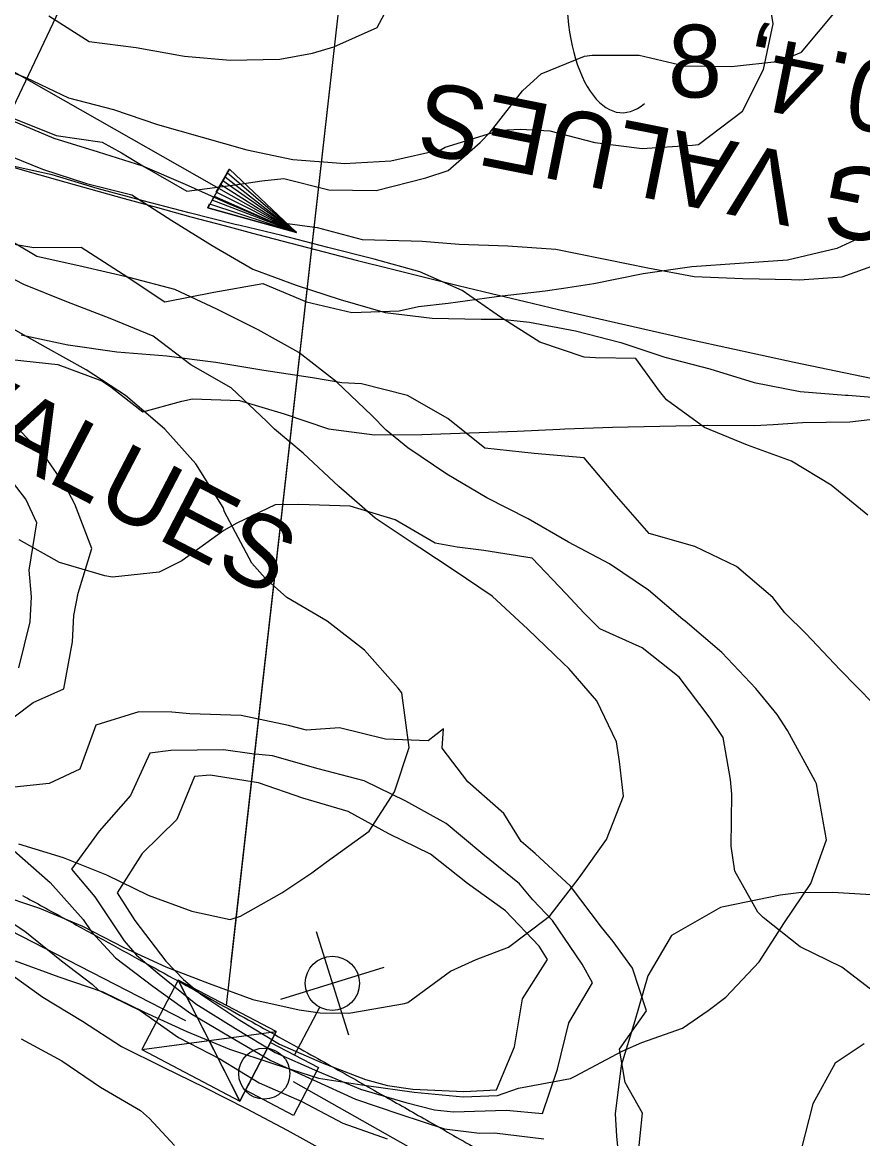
# Model space of a CAD drawing. Extents: x 1638506 to 1658005, y 834807 to 846788.
# Drawn here: x 1640269.4 to 1640408.1, y 842523.2 to 842707.5 of the extents above; entities that cross this region are included whole.
import ezdxf

# ---------------------------------------------------------------- set-up
doc = ezdxf.new("R2010")
doc.units = 0
for name, color, linetype in [('Default', 7, 'Continuous'), ('Old_Level_1', 7, 'Continuous'), ('Old_Level_2', 7, 'Continuous'), ('Scratch_Level_0', 7, 'Continuous')]:
    doc.layers.add(name, color=color, linetype=linetype)

msp = doc.modelspace()

# ---------------------------------------------------------------- linework, layer by layer
at = {"layer": 'Default'}
for p, q in [((1640114.23, 842786.79), (1640314.63, 842672.83)), ((1640303.08, 842545.23), (1640327.81, 842764.74)), ((1640303.88, 842552.36), (1640327.15, 842758.82)), ((1640060.76, 842664.16), (1640296.3, 842542.72)), ((1640317.9, 842557.44), (1640323.23, 842540.37)), ((1640312.05, 842546.24), (1640329.11, 842551.55)), ((1640295.12, 842549.41), (1640305.28, 842529.43)), ((1640320.57, 842548.92), (1640320.57, 842548.92)), ((1640316.26, 842547.55), (1640316.26, 842547.55)), ((1640314.33, 842537.04), (1640318.49, 842544.96)), ((1640289.09, 842537.94), (1640311.31, 842540.91)), ((1640314.09, 842532.64), (1640637.56, 842350.59))]:
    msp.add_line(p, q, dxfattribs=at)
msp.add_lwpolyline([(1640301.77, 842680.14), (1640302.13, 842680.79), (1640314.63, 842672.83), (1640302.47, 842681.39), (1640302.84, 842682.03), (1640314.63, 842672.83), (1640303.2, 842682.67), (1640303.57, 842683.32), (1640314.63, 842672.83), (1640299.98, 842676.9), (1640300.3, 842677.57), (1640314.63, 842672.83), (1640300.71, 842678.19), (1640301.03, 842678.86), (1640314.63, 842672.83), (1640301.4, 842679.5), (1640303.57, 842683.32), (1640299.98, 842676.9), (1640314.63, 842672.83), (1640303.57, 842683.32)], dxfattribs=at)
for points in [[(1640289.09, 842537.94), (1640305.28, 842529.43), (1640311.31, 842540.91), (1640295.12, 842549.41)], [(1640300.2, 842539.42), (1640295.12, 842549.41), (1640289.09, 842537.94)], [(1640300.2, 842539.42), (1640311.31, 842540.91), (1640305.28, 842529.43)], [(1640306.22, 842531.22), (1640310.37, 842539.12), (1640318.29, 842534.96), (1640314.14, 842527.06)]]:
    msp.add_lwpolyline(points, close=True, dxfattribs=at)
msp.add_circle((1640320.56, 842548.88), 4.47, dxfattribs=at)
msp.add_ellipse((1640368.8, 842713.14), major_axis=(-0.49, -20.52), ratio=0.466223, start_param=4.712389, end_param=6.681485, dxfattribs=at)
at = {"layer": 'Old_Level_1'}
for points in [[(1640262.94, 842701.14), (1640270.07, 842698.37), (1640277.01, 842695.06), (1640284.45, 842693.14), (1640291.69, 842690.67), (1640299.08, 842688.6), (1640306.46, 842686.5), (1640314.01, 842684.89), (1640321.93, 842684.27), (1640322.53, 842684.23), (1640330.21, 842684.65), (1640338.49, 842686.56), (1640339.17, 842686.9), (1640348.33, 842689.72), (1640351.63, 842689.92), (1640356.44, 842689.63), (1640363.89, 842687.72), (1640371.67, 842686.72), (1640379.99, 842687.24), (1640380.97, 842687.38), (1640388.22, 842692.89), (1640391.7, 842699.76), (1640393.32, 842707.31), (1640391.9, 842715.97)], [(1640273.79, 842708.59), (1640280.4, 842704.37), (1640288.17, 842703.36), (1640295.82, 842702.02), (1640296.16, 842701.97), (1640303.69, 842701.27), (1640311.89, 842701.43), (1640317.29, 842702.42), (1640320.78, 842703.49), (1640327.93, 842706.69), (1640331.59, 842713.5)], [(1640267.53, 842691.39), (1640274.58, 842688.4), (1640281.91, 842686.15), (1640289.21, 842683.84), (1640296.24, 842680.8), (1640303.26, 842677.7), (1640310.32, 842674.73), (1640318.07, 842673.67), (1640325.49, 842671.69), (1640333.55, 842671.45), (1640335.36, 842671.42), (1640341.49, 842670.93), (1640349.53, 842670.64), (1640357.46, 842670.07), (1640365.05, 842668.55), (1640366.15, 842668.35), (1640372.64, 842667.02), (1640380.24, 842665.55), (1640388.27, 842665.24), (1640396.35, 842665.06), (1640397.65, 842665.03), (1640404.66, 842665.52), (1640411.74, 842668.04)], [(1640265.63, 842686.17), (1640272.72, 842683.27), (1640280.01, 842680.93), (1640287.46, 842679.03), (1640294.06, 842674.8), (1640300.7, 842670.69), (1640307.42, 842666.77), (1640314.61, 842664.15), (1640321.87, 842661.75), (1640329.25, 842659.64), (1640337.04, 842658.68), (1640345.12, 842658.51), (1640348.47, 842658.51), (1640353.09, 842658.05), (1640360.69, 842656.58), (1640368.15, 842654.7), (1640375.41, 842652.28), (1640382.85, 842650.35), (1640390.16, 842648.06), (1640397.77, 842646.61), (1640405.22, 842645.99), (1640405.68, 842645.97), (1640413.58, 842645.32)], [(1640400.44, 842581.8), (1640400.21, 842582.25), (1640395.67, 842590.62), (1640393.98, 842593.25), (1640390.45, 842597.53), (1640384.8, 842603.52), (1640378.75, 842608.65), (1640378.41, 842608.95), (1640372.71, 842613.79), (1640366.3, 842618.14), (1640359.51, 842621.69), (1640352.89, 842625.58), (1640346.04, 842629.01), (1640339.44, 842632.95), (1640333.02, 842637.29), (1640329.43, 842640.23), (1640327.06, 842642.6), (1640321.23, 842648.2), (1640315.04, 842653.02), (1640308.33, 842656.75), (1640301.5, 842660.19), (1640294.56, 842663.42), (1640287.04, 842665.39), (1640279.44, 842667.19), (1640271.78, 842668.87), (1640265.17, 842672.79)], [(1640368.61, 842579.76), (1640367.96, 842585.5), (1640367.43, 842588.75), (1640364.2, 842595.54), (1640359.6, 842600.84), (1640358.65, 842601.74), (1640352.82, 842607.33), (1640346.92, 842612.79), (1640340.5, 842617.13), (1640334.98, 842620.77), (1640334.06, 842621.4), (1640327.62, 842625.7), (1640321.61, 842630.91), (1640315.72, 842636.38), (1640311.03, 842640.37), (1640309.72, 842641.63), (1640303.86, 842647.17), (1640297.22, 842651.01), (1640290.98, 842655.74), (1640283.89, 842658.63), (1640276.74, 842661.4), (1640269.62, 842664.23), (1640262.82, 842667.75)], [(1640332, 842596.83), (1640331.41, 842597.63), (1640325.88, 842603.88), (1640319.68, 842608.68), (1640313.06, 842612.59), (1640309.45, 842615.79), (1640307.27, 842618.26), (1640302.78, 842626.73), (1640302.53, 842627.45), (1640298.04, 842634.66), (1640292.9, 842640.39), (1640292.45, 842640.78), (1640286.41, 842645.95), (1640279.93, 842650.15), (1640273.23, 842653.88), (1640266.54, 842657.64)], [(1640277.68, 842605.28), (1640277.9, 842609.58), (1640278.62, 842613.28), (1640280.84, 842620.69), (1640278.05, 842628), (1640276.34, 842631.23), (1640273.22, 842635.75), (1640267.53, 842641.66)], [(1640270.68, 842608.54), (1640270.91, 842612.7), (1640270.51, 842617.07), (1640271.79, 842624.91), (1640269.98, 842628.81), (1640264.7, 842635.58)], [(1640268.84, 842600.96), (1640270.68, 842608.54)], [(1640268.05, 842592.89), (1640271.21, 842595.25), (1640276.27, 842597.5), (1640277.68, 842605.28)], [(1640268.78, 842571.93), (1640276.16, 842569.65), (1640283.27, 842566.81), (1640290.15, 842563.45), (1640297.35, 842560.78), (1640303.67, 842559.4), (1640305.42, 842559.99), (1640312.24, 842563.84), (1640317.18, 842567.12), (1640319.51, 842568.89), (1640326.64, 842574.01), (1640330.83, 842580.49), (1640333.23, 842587.82), (1640332, 842596.83)], [(1640268.21, 842552.59), (1640275.41, 842549.95), (1640282.7, 842547.48), (1640289.57, 842544.11), (1640296.52, 842540.92), (1640303.6, 842537.99), (1640310.92, 842535.59), (1640318.26, 842533.23), (1640326.14, 842532.02), (1640326.2, 842532.01), (1640334.06, 842530.9), (1640342.13, 842530.12), (1640347.81, 842530.37), (1640351.26, 842531.58), (1640359.88, 842533.18), (1640360.61, 842533.55), (1640368.38, 842537.67), (1640371.64, 842539.09), (1640378.32, 842541.47), (1640382.55, 842544.38), (1640385.49, 842546.57), (1640390.99, 842552.44), (1640395.19, 842558.92), (1640399.54, 842565.34), (1640402.1, 842572.58), (1640400.44, 842581.8)], [(1640264.94, 842563.69), (1640272.24, 842561.26), (1640279.31, 842558.3), (1640286.12, 842554.8), (1640293.05, 842551.58), (1640300.22, 842548.84), (1640307.42, 842546.19), (1640315.08, 842544.52), (1640318.52, 842544.03), (1640323.25, 842543.93), (1640332.46, 842545.57), (1640333.03, 842545.71), (1640340.07, 842550.86), (1640344.27, 842552.79), (1640349.61, 842554.86), (1640355.88, 842559.6), (1640356.49, 842560.09), (1640361.27, 842566.3), (1640365.81, 842572.62), (1640368.61, 842579.76)], [(1640411.32, 842563.4), (1640403.1, 842563.88), (1640397.55, 842563.83), (1640394.45, 842563.43), (1640385.12, 842561.52), (1640384.63, 842561.41), (1640376.5, 842556.76), (1640372.6, 842550.14), (1640370.47, 842542.69), (1640368.21, 842535.31), (1640367.24, 842527.31), (1640367.46, 842523.66), (1640367.95, 842518.54)], [(1640408.34, 842538.91), (1640403.52, 842535.72), (1640399.85, 842528.99), (1640397.93, 842521.45), (1640396.24, 842513.79), (1640396.26, 842513.01), (1640396.66, 842505.16), (1640398.51, 842499.74), (1640399.73, 842495.28), (1640400.3, 842486.58), (1640400.57, 842486.05), (1640405.23, 842477.95), (1640408.35, 842474.38)]]:
    msp.add_lwpolyline(points, dxfattribs=at)
at = {"layer": 'Old_Level_2'}
msp.add_line((1640319.78, 842802.51), (1640164.82, 842477.58), dxfattribs=at)
msp.add_arc((1640787.74, 844492.39), 1882, 251.76578, 273.94492, dxfattribs=at)
msp.add_open_spline([(1640269.4, 842563.39), (1640311.31, 842540.44), (1640352.83, 842516.74), (1640394.38, 842493.02)], degree=2, dxfattribs=at)
at = {"layer": 'Scratch_Level_0'}
for points in [[(1640267.74, 842691.75), (1640274.97, 842688.86), (1640282.55, 842687.76), (1640285.77, 842685.99), (1640289.54, 842683.7), (1640296.53, 842679.66), (1640304.54, 842680.71), (1640308.91, 842681.38), (1640312.56, 842681.78), (1640319.98, 842679.89), (1640327.76, 842679.79), (1640335.98, 842681.89), (1640339.67, 842683.05), (1640344.94, 842687.69), (1640346.66, 842689.46), (1640351.94, 842696.21), (1640355, 842699.06), (1640362.14, 842701.97), (1640363.41, 842702.11), (1640371.21, 842702.09), (1640378.67, 842700.38), (1640386.44, 842700.22), (1640394.42, 842701.15), (1640397.96, 842702.63), (1640403.58, 842709.31)], [(1640408.9, 842626.15), (1640402.86, 842631.1), (1640396.3, 842635.07), (1640389.05, 842637.71), (1640381.94, 842640.62), (1640375.71, 842645.23), (1640374.54, 842646.64), (1640370.63, 842652.03), (1640363.96, 842652.14), (1640362.13, 842652.28), (1640354.78, 842654.73), (1640348.31, 842658.86), (1640341.99, 842663.28), (1640334.97, 842666.36), (1640327.44, 842668.46), (1640319.81, 842670.38), (1640312.21, 842672.35), (1640305.34, 842673.97), (1640304.54, 842674.17), (1640296.9, 842676.06), (1640289.33, 842678.08), (1640281.76, 842680.1), (1640274.32, 842682.37), (1640271.32, 842683.02), (1640266.58, 842684.06)], [(1640263.73, 842671.6), (1640271.28, 842670.38), (1640279.09, 842670.4), (1640286.01, 842665.98), (1640292.89, 842661.37), (1640301.01, 842662.99), (1640309.1, 842664.42), (1640316.3, 842661.41), (1640323.75, 842659.64), (1640331.6, 842659.91), (1640334.76, 842660.63), (1640339.65, 842661.16), (1640347.67, 842662.25), (1640355.66, 842663.21), (1640358.71, 842663.65), (1640363.7, 842664.42), (1640371.83, 842666.09), (1640379.86, 842667.23), (1640379.89, 842667.23), (1640387.77, 842667.79), (1640395.68, 842668.32), (1640403.83, 842670.26), (1640403.87, 842670.27), (1640412.45, 842674.19)], [(1640409.93, 842594.94), (1640404.3, 842600.69), (1640398.73, 842606.56), (1640395.24, 842610.03), (1640393.23, 842612.57), (1640387.27, 842617.69), (1640380.35, 842620.97), (1640372.85, 842623.12), (1640367.44, 842629.3), (1640362.11, 842635.64), (1640353.86, 842636.35), (1640345.69, 842637.22), (1640339.62, 842642.12), (1640332.96, 842645.9), (1640325.34, 842647.83), (1640322.11, 842648.02), (1640317.26, 842648.87), (1640309.26, 842650.06), (1640301.31, 842651.36), (1640298.26, 842651.78), (1640293.25, 842652.44), (1640284.98, 842653.1), (1640276.95, 842654.24), (1640276.92, 842654.25), (1640269.19, 842655.91)], [(1640267.6, 842651.88), (1640275.23, 842651.06), (1640282.5, 842648.37), (1640284.01, 842647.34), (1640289.28, 842643.25), (1640295.71, 842645.01), (1640297.5, 842645.38), (1640305.24, 842645.08), (1640312.61, 842642.91), (1640319.92, 842640.43), (1640327.52, 842639.42), (1640335.33, 842639.51), (1640343.19, 842639.79), (1640351.04, 842640.02), (1640358.09, 842640.38), (1640358.91, 842640.4), (1640366.78, 842640.72), (1640374.61, 842640.89), (1640382.44, 842641.05), (1640390.22, 842640.95), (1640393.29, 842641.16), (1640398.13, 842641.48), (1640405.95, 842641.59), (1640413.94, 842642.52)], [(1640410.79, 842546.81), (1640404.63, 842551.54), (1640397.74, 842554.88), (1640391.65, 842559.74), (1640390.75, 842560.64), (1640387, 842567.38), (1640386.39, 842571.52), (1640386.49, 842580.09), (1640386.26, 842582.55), (1640385.05, 842589.46), (1640382.9, 842592.68), (1640377.8, 842599.45), (1640371.67, 842604.25), (1640364.69, 842607.41), (1640362.09, 842610.01), (1640359.11, 842613.26), (1640353.52, 842619.09), (1640345.53, 842620.31), (1640341.15, 842620.88), (1640337.53, 842621.52), (1640330.93, 842625.4), (1640323.49, 842627.66), (1640315.01, 842627.94), (1640311.14, 842627.85), (1640304.79, 842624.87), (1640302.65, 842623.64), (1640295.69, 842618.63), (1640291.95, 842616.74), (1640284.29, 842615.94), (1640283.03, 842616.16), (1640275.55, 842618.35), (1640268.86, 842622.07)], [(1640370.97, 842519.93), (1640371.73, 842527.42), (1640368.88, 842532.49), (1640367.93, 842538.01), (1640372.37, 842544.32), (1640370.06, 842551.37), (1640366.88, 842555.8), (1640364.95, 842558.13), (1640359.85, 842564.89), (1640354.03, 842570.3), (1640351.69, 842572.31), (1640348.86, 842576.94), (1640342.93, 842582.12), (1640338.7, 842587.68), (1640338.87, 842590.89), (1640336.34, 842588.9), (1640329.35, 842589.17), (1640321.71, 842591.04), (1640316.29, 842590.7), (1640313.3, 842591.46), (1640305.53, 842593.1), (1640297.06, 842593.39), (1640294.05, 842593.63), (1640288.6, 842593.69), (1640281.5, 842591.52), (1640278.9, 842584.26), (1640273.83, 842581.86), (1640268.04, 842581.27)], [(1640363.46, 842548.95), (1640361.8, 842552.06), (1640356.91, 842559.24), (1640353.66, 842562.66), (1640351.43, 842565.29), (1640345.37, 842570.21), (1640339.36, 842575.24), (1640332.66, 842578.94), (1640325.78, 842582.3), (1640318.21, 842584.31), (1640310.7, 842586.45), (1640307.27, 842586.76), (1640302.6, 842587.45), (1640293.91, 842587.32), (1640290.41, 842586.9), (1640287.26, 842579.91), (1640282.08, 842573.98), (1640277.49, 842567.75), (1640281.37, 842563.18), (1640286.21, 842555.89), (1640288.25, 842553.54), (1640291.96, 842550.37), (1640298.04, 842545.48), (1640304.55, 842541.41), (1640311.13, 842537.48), (1640318.12, 842534.36), (1640325.2, 842531.38), (1640332.69, 842529.21), (1640337.42, 842528), (1640340.52, 842527.68), (1640349.26, 842527.91), (1640355.23, 842527.37), (1640357.69, 842534.71), (1640359.56, 842542.36), (1640363.46, 842548.95)], [(1640356.05, 842552.8), (1640354.71, 842555.01), (1640349.11, 842560.82), (1640342.83, 842565.34), (1640336.74, 842570.21), (1640329.87, 842573.56), (1640323.17, 842577.26), (1640315.68, 842579.44), (1640308.38, 842581.98), (1640300.4, 842583.22), (1640297.83, 842583.04), (1640294.89, 842575.95), (1640289.19, 842570.29), (1640285.06, 842563.82), (1640287.94, 842559.24), (1640293.09, 842552.54), (1640296.01, 842549.51), (1640298.87, 842547.09), (1640305.28, 842542.82), (1640311.82, 842538.81), (1640318.86, 842535.77), (1640326.03, 842532.98), (1640329.65, 842532.03), (1640333.82, 842531.39), (1640342.25, 842531.03), (1640347.66, 842531.3), (1640350.59, 842538.4), (1640351.93, 842546.32), (1640356.05, 842552.8)], [(1640268.05, 842570.73), (1640273.97, 842565.52), (1640279.42, 842559.43), (1640280.81, 842557.4), (1640284.75, 842553.08), (1640290.94, 842548.41), (1640297.21, 842543.87), (1640303.82, 842540), (1640310.43, 842536.15), (1640317.39, 842532.95), (1640324.36, 842529.77), (1640331.67, 842527.25), (1640339.06, 842524.87), (1640344.85, 842524.14), (1640347.31, 842524.17), (1640355.43, 842523.21)], [(1640263.37, 842561.72), (1640269.8, 842557.5), (1640275.86, 842552.57), (1640280.94, 842548.71), (1640281.99, 842547.77), (1640288.85, 842544.38), (1640295.15, 842539.91), (1640301.96, 842536.43), (1640308.5, 842532.42), (1640315.54, 842529.38), (1640322.3, 842525.81), (1640329.58, 842523.22)], [(1640266.48, 842551.1), (1640272.76, 842546.6), (1640279.33, 842542.65), (1640285.78, 842538.47), (1640292.62, 842535.05), (1640299.5, 842531.7), (1640306.32, 842528.23), (1640313.08, 842524.65), (1640319.78, 842520.94)], [(1640269.18, 842539.7), (1640275.93, 842536.1), (1640282.27, 842531.72), (1640288.89, 842527.86), (1640290.38, 842526.57), (1640294.52, 842522.1)]]:
    msp.add_lwpolyline(points, dxfattribs=at)
msp.add_circle((1640309.31, 842533.98), 4.21, dxfattribs=at)

# ---------------------------------------------------------------- texts
at = {"layer": 'Default'}
msp.add_text('8', height=12, dxfattribs=at).set_placement((1640375.93, 842695.13))
at = {"layer": 'Scratch_Level_0'}
for s, rotation, p in [('0.8, 1.0, 1.2', 168.7284, (1640470.05, 842708)), ('0.1, 0.2, 0.4,', 168.7284, (1640476.9, 842688.28)), ('RING VALUES', 168.7284, (1640442.03, 842676.88)), ('RING VALUES', 332.5519, (1640214.56, 842662.3))]:
    msp.add_text(s, height=12, rotation=rotation, dxfattribs=at).set_placement(p)

doc.saveas('drawing.dxf')
